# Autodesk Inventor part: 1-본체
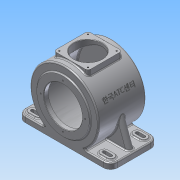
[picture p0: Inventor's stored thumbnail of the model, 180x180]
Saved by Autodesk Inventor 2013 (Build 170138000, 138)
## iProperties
Created: 2015-06
Part Number: 1-본체
Material: 알루미늄 6061
Document SubType Name: Modeling
Designer: ST5
Density: 2.71 g/cm^3
Mass: 3341.58 g
Surface Area: 2297.32 cm^2
Volume: 1233.06 cm^3
Author: ST5
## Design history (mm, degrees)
sketch "스케치1"
  geometry: L1 (-115, 59)-(115, 59); L2 (115, 59)-(115, -59); L3 (115, -59)-(-115, -59); L4 (-115, -59)-(-115, 59); 3 further points
  constraints: 8 end point, 2 midpoint, 2 parallel, 1 horizontal, 1 horizontal alignment, 1 perpendicular, 1 vertical alignment
  dimensions: "d0" = 230 distance of L1.start L1.end; "d2" = 118 distance of L3.end L1.start
extrude "돌출1" new body sketch "스케치1" distance "d3" = 14; taper "d4" = 0 deg
node "작업 평면1"
sketch "스케치2"
  geometry: L1 (115, 0)-(-115, 0) reference; C1 r 85 at (0, 85); 2 further points
  constraints: 1 centre point, 1 midpoint, 1 vertical alignment
  dimensions: "d6" = 170 diameter of C1; "d8" = 85 distance of point (0, 0) C1.centre
extrude "돌출2" join sketch "스케치2" stored distance "d9" = 118; taper "d10" = 0 deg
node "작업 평면2"
sketch "스케치3"
  geometry: L1 (-42.5, 42.5)-(42.5, 42.5); L2 (42.5, 42.5)-(42.5, -42.5); L3 (42.5, -42.5)-(-42.5, -42.5); L4 (-42.5, -42.5)-(-42.5, 42.5); 3 further points
  constraints: 8 end point, 2 midpoint, 2 parallel, 2 perpendicular, 1 horizontal, 1 horizontal alignment, 1 vertical alignment
  dimensions: "d12" = 85 distance of L1.start L1.end
extrude "돌출3" join sketch "스케치3" stored distance "d14" = 118; taper "d15" = 0 deg
node "작업 평면3"
sketch "스케치4"
  geometry: L1 (0, 14)-(68.267, 14) reference; L2 (0, 0)-(0, 14) reference; L3 (230, 0)-(0, 0) reference; L4 (230, 0)-(230, 14) reference; L5 (161.733, 14)-(230, 14) reference; L6 (6, 14)-(30.13, 80.297); L7 (0, 14)-(68.267, 14) reference; A1 r 85 centre (115, 85) between (161.733, 14) and (68.267, 14) reference; 1 further point
  constraints: 2 end point, 1 point on circle, 1 point on line
  dimensions: "d16" = 6 distance from line of L2 L6.start; "d17" = 110 deg angle of L1 L6
extrude "돌출4" join sketch "스케치4" stored distance "d18" = 15; taper "d19" = 0 deg
node "작업 평면4"
sketch "스케치5"
  geometry: C1 r 65 at (115, 85); A1 r 85 centre (115, 85) between (161.733, 14) and (68.267, 14) reference; 1 further point
  constraints: 1 centre point, 1 coincident
  dimensions: "d21" = 130 diameter of C1
extrude "돌출5" join sketch "스케치5" distance "d23" = 3; taper "d24" = 0 deg
sketch "스케치6"
  geometry: C1 r 65 at (0, 0) reference; C2 r 47.5 at (0, 0); 1 further point
  constraints: 1 centre point, 1 coincident
  dimensions: "d25" = 95 diameter of C2
extrude "돌출6" cut sketch "스케치6" distance "d27" = 11; taper "d28" = 0 deg
sketch "스케치7"
  geometry: C1 r 47.5 at (0, 0) reference; C2 r 77 at (0, 0); 1 further point
  constraints: 1 centre point, 1 coincident
  dimensions: "d29" = 154 diameter of C2
extrude "돌출7" cut sketch "스케치7" distance "d31" = 102; taper "d32" = 0 deg
sketch "스케치8"
  geometry: C1 r 77 at (0, 0) reference; C2 r 31 at (0, 0); 1 further point
  constraints: 1 centre point, 1 coincident
  dimensions: "d33" = 62 diameter of C2
extrude "돌출8" join sketch "스케치8" distance "d35" = 3.5; taper "d36" = -25 deg
sketch "스케치9"
  geometry: C1 r 65 at (115, -85); A1 r 85 centre (115, -85) between (68.267, -14) and (161.733, -14) reference; 1 further point
  constraints: 1 centre point, 1 coincident
  dimensions: "d37" = 130 diameter of C1
extrude "돌출9" join sketch "스케치9" distance "d39" = 13; taper "d40" = 0 deg
sketch "스케치10"
  geometry: C1 r 29.368 at (0, 0) reference; C2 r 23.5 at (0, 0); 1 further point
  constraints: 1 centre point, 1 coincident
  dimensions: "d41" = 47 diameter of C2
extrude "돌출10" cut sketch "스케치10" distance "d43" = 14; taper "d44" = 0 deg
sketch "스케치11"
  geometry: C1 r 23.5 at (0, 0) reference; C2 r 15 at (0, 0); 1 further point
  constraints: 1 centre point, 1 coincident
  dimensions: "d45" = 30 diameter of C2
extrude "돌출11" cut sketch "스케치11" distance "d47" = 3; taper "d48" = 0 deg
fillet "모깎기1" dims "d49" = 0.3
fillet "모깎기2" dims "d50" = 3
chamfer "모따기1" distance "d51" = 1; stored, may be unused: second distance "d52" = 2, angle "d53" = 45 deg
fillet "모깎기4" dims "d55" = 3
fillet "모깎기5" dims "d56" = 3
fillet "모깎기6" dims "d57" = 3
fillet "모깎기7" dims "d58" = 7.5
fillet "모깎기8" dims "d59" = 7
fillet "모깎기9" dims "d60" = 18
sketch "스케치12"
  geometry: C1 r 65 at (0, 0) reference; 2 further points
  constraints: 1 vertical alignment
  dimensions: "d61" = 55 distance of C1.centre point (0, 55)
hole "구멍1" sketch "스케치12" at (0, 55) diameter "d62" = 3.459; stored, may be unused: countersink angle "d66" = 90 deg, drill point angle "d68" = 118 deg; dims "d63" = 20, "d64" = 4, "d65" = 2, "d67" = 20
sketch "스케치13"
  geometry: A1 r 7 centre (-35.5, 35.5) between (-35.5, 42.5) and (-42.5, 35.5) reference; A2 r 7 centre (-35.5, -35.5) between (-42.5, -35.5) and (-35.5, -42.5) reference; A3 r 7 centre (35.5, -35.5) between (35.5, -42.5) and (42.5, -35.5) reference; A4 r 7 centre (35.5, 35.5) between (42.5, 35.5) and (35.5, 42.5) reference; 5 further points
  constraints: 4 coincident
hole "구멍2" sketch "스케치13" at (-35.5, 35.5), (35.5, 35.5), (35.5, -35.5), (-35.5, -35.5) diameter "d72" = 3.459; stored, may be unused: countersink angle "d76" = 90 deg, drill point angle "d78" = 118 deg; dims "d73" = 10, "d74" = 4, "d75" = 2, "d77" = 13
sketch "스케치14"
  geometry: C1 r 35 at (0, 0); 1 further point
  constraints: 1 centre point, 1 coincident
  dimensions: "d79" = 70 diameter of C1
extrude "돌출12" cut sketch "스케치14" distance "d81" = 20; taper "d82" = 0 deg
chamfer "모따기2" distance "d83" = 1; stored, may be unused: second distance "d84" = 2, angle "d85" = 45 deg
fillet "모깎기10" dims "d86" = 3
fillet "모깎기11" dims "d87" = 3
node "작업 평면5"
sketch "스케치15"
  geometry: L1 (0, 85)-(77.036, 120.923); C1 r 12 at (0, 85) reference; A1 r 85 centre (0, 85) between (46.733, 14) and (-46.733, 14) reference; 3 further points
  constraints: 2 end point, 2 horizontal alignment, 1 point on circle, 1 other
  dimensions: "d91" = 25 deg dimension on L1.start L1.end point (74, 85)
  node "투영된 루프2"
fillet "모깎기14" dims "d94" = 3
fillet "모깎기15" dims "d95" = 3
fillet "모깎기16" dims "d96" = 2.7
node "작업 평면7"
sketch "스케치17"
  geometry: L1 (112.3, 41)-(112.3, -41) reference; L2 (81, 50)-(97, 50); L3 (97, 32)-(81, 32); L4 (97, 59)-(55.845, 59) reference; L5 (115, -41)-(115, 41) reference; A1 r 9 centre (97, 41) between (97, 32) and (97, 50); A2 r 9 centre (81, 41) between (81, 50) and (81, 32); 1 further point
  constraints: 4 end point, 4 point on circle, 4 tangent, 2 centre point, 1 parallel, 1 perpendicular
  dimensions: "d97" = 9 radius of A2; "d99" = 16 distance of A2.centre A1.centre; "d100" = 18 distance from line of L4 A1.centre; "d101" = 18 distance from line of L5 A1.centre
extrude "돌출13" join sketch "스케치17" distance "d102" = 3; taper "d103" = 0 deg
sketch "스케치18"
  geometry: L1 (81, 45)-(97, 45); L2 (81, 37)-(97, 37); A1 r 9 centre (81, 41) between (81, 50) and (81, 32) reference; A2 r 9 centre (97, 41) between (97, 32) and (97, 50) reference; A3 r 4 centre (81, 41) between (81, 45) and (81, 37); A4 r 4 centre (97, 41) between (97, 37) and (97, 45); 1 further point
  constraints: 4 end point, 4 point on circle, 4 tangent, 2 centre point, 2 coincident, 1 equal radius
  dimensions: "d104" = 8 diameter of A3
extrude "돌출14" cut sketch "스케치18" stored distance "d106" = 3; taper "d107" = 0 deg
node "작업 평면8"
node "작업 평면9"
fillet "모깎기17" dims "d108" = 18
fillet "모깎기18" dims "d109" = 2.5
fillet "모깎기19" dims "d110" = 2.5
sketch "스케치19"
  geometry: L1 (81, 45)-(97, 45) reference; L2 (97, 37)-(81, 37) reference; L3 (81, 45)-(97, 45); L4 (81, 37)-(97, 37); A1 r 4 centre (81, 41) between (81, 45) and (81, 37) reference; A2 r 4 centre (97, 41) between (97, 37) and (97, 45) reference; A3 r 4 centre (97, 41) between (97, 37) and (97, 45); A4 r 4 centre (81, 41) between (81, 45) and (81, 37); 1 further point
  constraints: 8 tangent, 4 end point, 4 point on circle, 2 centre point, 2 coincident, 2 collinear, 1 concentric, 1 point on line
extrude "돌출15" cut sketch "스케치19" stored distance "d111" = 3; taper "d112" = 0 deg
node "작업 평면10"
fillet "모깎기20" dims "d114" = 3
sketch "스케치20"
  geometry: L1 (0, 85)-(77.036, 120.923); C1 r 12 at (0, 85) reference; A1 r 85 centre (0, 85) between (53.953, 19.318) and (-53.953, 19.318) reference; 2 further points
  constraints: 2 end point, 2 horizontal alignment, 1 point on circle, 1 other
  dimensions: "d115" = 25 deg dimension on C1.centre point (62, 85) L1.end
  node "투영된 루프4"
node "작업 평면11"
sketch "스케치21"
  geometry: L1 (-35.5, 47.366)-(35.5, 47.366) reference; L2 (56, -36.727)-(56, 85) reference; L3 (59, -80.996)-(59, -42.262) reference; L4 (56, 85)-(56, 85) reference; 4 further points
  constraints: 1 horizontal alignment, 1 midpoint, 1 point on line, 1 vertical alignment, 3 other
feature "엠보싱2" sketch "스케치21" dims "d116" = 0.5, "d117" = 0
node "작업 평면12"
sketch "스케치22"
  geometry: L1 (85.201, 14)-(144.799, 14); C1 r 12 at (115, 85) reference; A1 r 77 centre (115, 85) between (144.799, 14) and (85.201, 14) reference; A2 r 77 centre (115, 85) between (85.201, 14) and (144.799, 14); 1 further point
  constraints: 2 end point, 2 point on circle, 1 centre point, 1 coincident, 1 concentric, 1 horizontal
extrude "돌출16" cut sketch "스케치22" stored distance "d119" = 102; taper "d120" = 0 deg
fillet "모깎기21" dims "d121" = 3
chamfer "모따기3" distance "d122" = 1; stored, may be unused: second distance "d123" = 2, angle "d124" = 45 deg
node "솔리드1"
mirror "대칭1"
pattern_circular "원형 패턴1" dims angle "d70" = 360 deg
mirror "대칭2"
mirror "대칭3"
mirror "대칭4"
mirror "대칭5"
mirror "대칭6"
node "투영된 루프1"
node "투영된 루프3"
node "투영된 루프5"
node "투영된 루프6"
other parameters: "d5" = 0, "d11" = 173, "d20" = 0, "d90" = 0, "d113" = 0, "d118" = 0
